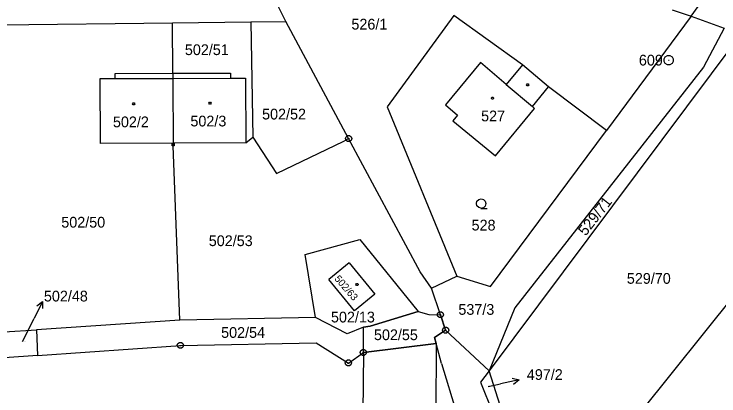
# Model space of a CAD drawing. Extents: x -759060 to -757386, y -1172273 to -1170948.
# Drawn here: x -758724.7 to -758613.1, y -1171917.2 to -1171856.8 of the extents above; entities that cross this region are included whole.
import ezdxf

# ---------------------------------------------------------------- set-up
doc = ezdxf.new("R2010")
doc.units = 0
for name, color, linetype in [('Vrstva 1', 7, 'Continuous'), ('Vrstva 12', 7, 'Continuous'), ('Vrstva 13', 7, 'Continuous'), ('Vrstva 2', 7, 'Continuous'), ('Vrstva 3', 7, 'Continuous'), ('Vrstva 4', 7, 'Continuous'), ('Vrstva 5', 7, 'Continuous'), ('Vrstva 7', 7, 'Continuous'), ('Vrstva 8', 7, 'Continuous')]:
    doc.layers.add(name, color=color, linetype=linetype)

msp = doc.modelspace()

# ---------------------------------------------------------------- linework, layer by layer
at = {"layer": 'Vrstva 1'}
for p, q in [((-758681.63, -1171857.97), (-758688.87, -1171843.64)), ((-758617.44, -1171857.11), (-758616.32, -1171855.59)), ((-758620.44, -1171856.14), (-758617.44, -1171857.11)), ((-758699.57, -1171858.18), (-758687.18, -1171858.03)), ((-758687.18, -1171858.03), (-758681.63, -1171857.97)), ((-758687.18, -1171858.03), (-758686.87, -1171876.27)), ((-758671.69, -1171876.51), (-758681.63, -1171857.97)), ((-758655.06, -1171857.01), (-758665.59, -1171871.5)), ((-758644.15, -1171864.85), (-758655.06, -1171857.01)), ((-758617.44, -1171857.11), (-758630.84, -1171875.22)), ((-758617.44, -1171857.11), (-758612.23, -1171859.02)), ((-758726.92, -1171858.5), (-758699.57, -1171858.18)), ((-758699.53, -1171866.17), (-758699.57, -1171858.18)), ((-758612.23, -1171859.02), (-758615.5, -1171865.18)), ((-758609.42, -1171859.7), (-758649.44, -1171913.23)), ((-758650.82, -1171864.46), (-758656.38, -1171871.16)), ((-758646.74, -1171867.94), (-758650.82, -1171864.46)), ((-758644.15, -1171864.85), (-758646.74, -1171867.94)), ((-758615.5, -1171865.18), (-758645.35, -1171903.31)), ((-758640.02, -1171868.34), (-758644.15, -1171864.85)), ((-758711.02, -1171867.01), (-758708.69, -1171867)), ((-758710.97, -1171877.29), (-758711.02, -1171867.01)), ((-758708.69, -1171866.21), (-758699.53, -1171866.17)), ((-758708.69, -1171867), (-758708.69, -1171866.21)), ((-758699.53, -1171866.17), (-758690.38, -1171866.14)), ((-758699.53, -1171866.17), (-758699.53, -1171866.97)), ((-758699.53, -1171866.97), (-758699.47, -1171877.64)), ((-758690.38, -1171866.14), (-758690.38, -1171866.94)), ((-758690.38, -1171866.94), (-758688.04, -1171866.94)), ((-758688.04, -1171866.94), (-758687.99, -1171877.18)), ((-758642.6, -1171871.41), (-758640.02, -1171868.34)), ((-758630.84, -1171875.22), (-758640.02, -1171868.34)), ((-758656.38, -1171871.16), (-758654.44, -1171872.8)), ((-758642.24, -1171871.75), (-758642.6, -1171871.41)), ((-758665.59, -1171871.5), (-758654.55, -1171898.27)), ((-758648.43, -1171879.21), (-758642.24, -1171871.75)), ((-758654.44, -1171872.8), (-758655.2, -1171873.68)), ((-758655.2, -1171873.68), (-758648.43, -1171879.21)), ((-758649.25, -1171899.92), (-758630.84, -1171875.22)), ((-758687.99, -1171877.18), (-758686.87, -1171876.27)), ((-758686.87, -1171876.27), (-758683.13, -1171882.02)), ((-758683.13, -1171882.02), (-758672.47, -1171876.89)), ((-758672.47, -1171876.89), (-758671.69, -1171876.51)), ((-758660.39, -1171897.59), (-758671.69, -1171876.51)), ((-758641.1, -1171939.36), (-758590.42, -1171876.04)), ((-758699.63, -1171877.24), (-758710.97, -1171877.29)), ((-758699.63, -1171877.64), (-758699.63, -1171877.24)), ((-758699.47, -1171877.64), (-758699.63, -1171877.64)), ((-758698.42, -1171905.23), (-758699.47, -1171877.64)), ((-758699.3, -1171877.64), (-758699.47, -1171877.64)), ((-758687.99, -1171877.18), (-758699.3, -1171877.24)), ((-758699.3, -1171877.24), (-758699.3, -1171877.64)), ((-758678.56, -1171894.85), (-758669.92, -1171892.47)), ((-758669.92, -1171892.47), (-758660.69, -1171903.85)), ((-758676.93, -1171904.8), (-758678.56, -1171894.85)), ((-758671.62, -1171896.16), (-758674.84, -1171898.79)), ((-758671.62, -1171896.16), (-758667.54, -1171901.15)), ((-758658.59, -1171900.15), (-758660.39, -1171897.59)), ((-758658.59, -1171900.15), (-758654.55, -1171898.27)), ((-758654.55, -1171898.27), (-758649.25, -1171899.92)), ((-758670.75, -1171903.77), (-758674.84, -1171898.79)), ((-758657.16, -1171904.38), (-758658.59, -1171900.15)), ((-758667.54, -1171901.15), (-758670.75, -1171903.77)), ((-758660.69, -1171903.85), (-758668.27, -1171906.2)), ((-758660.69, -1171903.85), (-758659, -1171904.32)), ((-758645.35, -1171903.31), (-758649.44, -1171913.23)), ((-758676.93, -1171904.8), (-758698.42, -1171905.23)), ((-758671.94, -1171907.4), (-758676.93, -1171904.8)), ((-758659, -1171904.32), (-758657.16, -1171904.38)), ((-758656.33, -1171906.83), (-758657.16, -1171904.38)), ((-758698.42, -1171905.23), (-758721.14, -1171906.79)), ((-758726.24, -1171907.11), (-758721.14, -1171906.79)), ((-758721.14, -1171906.79), (-758720.99, -1171910.81)), ((-758669.33, -1171906.33), (-758671.94, -1171907.4)), ((-758669.36, -1171910.35), (-758669.33, -1171906.33)), ((-758668.27, -1171906.2), (-758669.33, -1171906.33)), ((-758658.08, -1171907.96), (-758656.33, -1171906.83)), ((-758656.33, -1171906.83), (-758649.44, -1171913.23)), ((-758657.83, -1171908.92), (-758658.08, -1171907.96)), ((-758720.99, -1171910.81), (-758698.34, -1171909.23)), ((-758698.34, -1171909.23), (-758676.85, -1171908.8)), ((-758676.85, -1171908.8), (-758671.73, -1171912.02)), ((-758669.36, -1171910.35), (-758657.83, -1171908.92)), ((-758657.83, -1171908.92), (-758657.93, -1171926.59)), ((-758657, -1171912.1), (-758657.83, -1171908.92)), ((-758671.73, -1171912.02), (-758669.36, -1171910.35)), ((-758669.36, -1171910.35), (-758669.48, -1171926.67)), ((-758720.99, -1171910.81), (-758726.18, -1171911.22)), ((-758657, -1171912.1), (-758649.11, -1171937.91)), ((-758649.44, -1171913.23), (-758650.8, -1171915.04)), ((-758641.1, -1171939.36), (-758649.44, -1171913.23)), ((-758650.8, -1171915.04), (-758641.1, -1171939.36))]:
    msp.add_line(p, q, dxfattribs=at)
at = {"layer": 'Vrstva 12'}
for p, q in [((-758650.82, -1171864.46), (-758656.38, -1171871.16)), ((-758646.74, -1171867.94), (-758650.82, -1171864.46)), ((-758711.02, -1171867.01), (-758708.69, -1171867)), ((-758710.97, -1171877.29), (-758711.02, -1171867.01)), ((-758708.69, -1171867), (-758699.53, -1171866.97)), ((-758699.53, -1171866.97), (-758690.38, -1171866.94)), ((-758699.53, -1171866.97), (-758699.47, -1171877.64)), ((-758699.53, -1171866.97), (-758699.47, -1171877.64)), ((-758690.38, -1171866.94), (-758688.04, -1171866.94)), ((-758688.04, -1171866.94), (-758687.99, -1171877.18)), ((-758646.74, -1171867.94), (-758642.6, -1171871.41)), ((-758656.38, -1171871.16), (-758654.44, -1171872.8)), ((-758642.24, -1171871.75), (-758642.6, -1171871.41)), ((-758648.43, -1171879.21), (-758642.24, -1171871.75)), ((-758654.44, -1171872.8), (-758655.2, -1171873.68)), ((-758655.2, -1171873.68), (-758648.43, -1171879.21)), ((-758699.63, -1171877.24), (-758710.97, -1171877.29)), ((-758699.63, -1171877.64), (-758699.63, -1171877.24)), ((-758699.47, -1171877.64), (-758699.63, -1171877.64)), ((-758699.3, -1171877.64), (-758699.47, -1171877.64)), ((-758687.99, -1171877.18), (-758699.3, -1171877.24)), ((-758699.3, -1171877.24), (-758699.3, -1171877.64)), ((-758671.62, -1171896.16), (-758674.84, -1171898.79)), ((-758671.62, -1171896.16), (-758667.54, -1171901.15)), ((-758670.75, -1171903.77), (-758674.84, -1171898.79)), ((-758667.54, -1171901.15), (-758670.75, -1171903.77))]:
    msp.add_line(p, q, dxfattribs=at)
at = {"layer": 'Vrstva 13'}
for p, q in [((-758668.27, -1171906.2), (-758660.69, -1171903.85)), ((-758660.69, -1171903.85), (-758659, -1171904.32)), ((-758659, -1171904.32), (-758657.16, -1171904.38)), ((-758657.16, -1171904.38), (-758656.33, -1171906.83)), ((-758669.36, -1171910.35), (-758669.33, -1171906.33)), ((-758669.33, -1171906.33), (-758668.27, -1171906.2)), ((-758656.33, -1171906.83), (-758658.08, -1171907.96)), ((-758658.08, -1171907.96), (-758657.83, -1171908.92)), ((-758657.83, -1171908.92), (-758669.36, -1171910.35))]:
    msp.add_line(p, q, dxfattribs=at)
at = {"layer": 'Vrstva 3'}
msp.add_lwpolyline([(-758650.72, -1171887.53), (-758651.1, -1171887.43), (-758651.37, -1171887.16), (-758651.47, -1171886.79), (-758651.37, -1171886.42), (-758651.1, -1171886.15), (-758650.73, -1171886.05), (-758650.36, -1171886.15), (-758650.09, -1171886.42), (-758649.99, -1171886.8), (-758650.09, -1171887.18), (-758650.36, -1171887.45), (-758650.74, -1171887.55), (-758649.74, -1171887.55)], dxfattribs=at)
at = {"layer": 'Vrstva 4'}
for p, q in [((-758708.69, -1171867), (-758699.53, -1171866.97)), ((-758699.53, -1171866.97), (-758690.38, -1171866.94)), ((-758646.74, -1171867.94), (-758642.6, -1171871.41))]:
    msp.add_line(p, q, dxfattribs=at)
at = {"layer": 'Vrstva 5'}
for points in [[(-758643.24, -1171867.85), (-758643.15, -1171868), (-758643.24, -1171868.15), (-758643.42, -1171868.15), (-758643.51, -1171868), (-758643.42, -1171867.85)], [(-758648.82, -1171869.94), (-758648.73, -1171870.09), (-758648.82, -1171870.24), (-758649, -1171870.24), (-758649.09, -1171870.09), (-758649, -1171869.94)], [(-758705.66, -1171870.85), (-758705.57, -1171871), (-758705.66, -1171871.15), (-758705.84, -1171871.15), (-758705.93, -1171871), (-758705.84, -1171870.85)], [(-758693.57, -1171870.76), (-758693.48, -1171870.91), (-758693.57, -1171871.06), (-758693.75, -1171871.06), (-758693.84, -1171870.91), (-758693.75, -1171870.76)], [(-758670.26, -1171899.46), (-758670.17, -1171899.61), (-758670.26, -1171899.76), (-758670.44, -1171899.76), (-758670.53, -1171899.61), (-758670.44, -1171899.46)]]:
    msp.add_lwpolyline(points, close=True, dxfattribs=at)
at = {"layer": 'Vrstva 7'}
for p, q in [((-758720.185, -1171902.283), (-758721.52, -1171904.97)), ((-758723.33, -1171908.61), (-758721.52, -1171904.97)), ((-758644.712, -1171914.703), (-758647.65, -1171915.31)), ((-758649.61, -1171915.71), (-758647.65, -1171915.31))]:
    msp.add_line(p, q, dxfattribs=at)
for points in [[(-758721.078, -1171902.956), (-758720.185, -1171902.283), (-758720.182, -1171903.401)], [(-758645.792, -1171914.416), (-758644.712, -1171914.703), (-758645.59, -1171915.395)]]:
    msp.add_lwpolyline(points, dxfattribs=at)
at = {"layer": 'Vrstva 8'}
for p, q in [((-758621.05, -1171864.09), (-758620.95, -1171864.09)), ((-758671.81, -1171876.51), (-758671.57, -1171876.51)), ((-758657.28, -1171904.38), (-758657.04, -1171904.38)), ((-758656.45, -1171906.83), (-758656.21, -1171906.83)), ((-758698.46, -1171909.23), (-758698.22, -1171909.23)), ((-758669.48, -1171910.35), (-758669.24, -1171910.35)), ((-758671.85, -1171912.02), (-758671.61, -1171912.02))]:
    msp.add_line(p, q, dxfattribs=at)
for points in [[(-758620.81, -1171863.37), (-758620.47, -1171863.56), (-758620.28, -1171863.9), (-758620.28, -1171864.29), (-758620.47, -1171864.63), (-758620.81, -1171864.82), (-758621.2, -1171864.82), (-758621.54, -1171864.63), (-758621.73, -1171864.29), (-758621.73, -1171863.9), (-758621.54, -1171863.56), (-758621.2, -1171863.37)], [(-758671.54, -1171876.03), (-758671.29, -1171876.21), (-758671.19, -1171876.5), (-758671.29, -1171876.79), (-758671.54, -1171876.97), (-758671.85, -1171876.97), (-758672.1, -1171876.79), (-758672.2, -1171876.5), (-758672.1, -1171876.21), (-758671.85, -1171876.03)], [(-758657.01, -1171903.9), (-758656.76, -1171904.08), (-758656.66, -1171904.37), (-758656.76, -1171904.66), (-758657.01, -1171904.84), (-758657.32, -1171904.84), (-758657.57, -1171904.66), (-758657.67, -1171904.37), (-758657.57, -1171904.08), (-758657.32, -1171903.9)], [(-758656.18, -1171906.35), (-758655.93, -1171906.53), (-758655.83, -1171906.82), (-758655.93, -1171907.11), (-758656.18, -1171907.29), (-758656.49, -1171907.29), (-758656.74, -1171907.11), (-758656.84, -1171906.82), (-758656.74, -1171906.53), (-758656.49, -1171906.35)], [(-758698.19, -1171908.75), (-758697.94, -1171908.93), (-758697.84, -1171909.22), (-758697.94, -1171909.51), (-758698.19, -1171909.69), (-758698.5, -1171909.69), (-758698.75, -1171909.51), (-758698.85, -1171909.22), (-758698.75, -1171908.93), (-758698.5, -1171908.75)], [(-758669.21, -1171909.87), (-758668.96, -1171910.05), (-758668.86, -1171910.34), (-758668.96, -1171910.63), (-758669.21, -1171910.81), (-758669.52, -1171910.81), (-758669.77, -1171910.63), (-758669.87, -1171910.34), (-758669.77, -1171910.05), (-758669.52, -1171909.87)], [(-758671.58, -1171911.54), (-758671.33, -1171911.72), (-758671.23, -1171912.01), (-758671.33, -1171912.3), (-758671.58, -1171912.48), (-758671.89, -1171912.48), (-758672.14, -1171912.3), (-758672.24, -1171912.01), (-758672.14, -1171911.72), (-758671.89, -1171911.54)]]:
    msp.add_lwpolyline(points, close=True, dxfattribs=at)

# ---------------------------------------------------------------- texts
at = {"layer": 'Vrstva 2'}
for s, height, p in [('526/1', 1.7, (-758671.253, -1171859.25)), ('502/51', 1.7, (-758697.629, -1171863.29)), ('502/52', 1.7, (-758685.4, -1171873.48)), ('527', 1.7, (-758650.713, -1171873.77)), ('502/2', 1.7, (-758709.023, -1171874.71)), ('502/3', 1.7, (-758696.753, -1171874.58)), ('502/50', 1.7, (-758717.203, -1171890.59)), ('528', 1.7, (-758652.223, -1171891.05)), ('502/53', 1.7, (-758693.844, -1171893.52)), ('529/70', 1.7, (-758627.633, -1171899.48)), ('537/3', 1.7, (-758654.313, -1171904.39)), ('502/13', 1.7, (-758674.493, -1171905.6)), ('502/54', 1.7, (-758691.887, -1171908.04)), ('502/55', 1.7, (-758667.684, -1171908.4)), ('502/48', 0.1, (-758723.316, -1171908.61)), ('497/2', 0.1, (-758649.596, -1171915.71))]:
    msp.add_text(s, height=height, dxfattribs=at).set_placement(p)
for s, height, rotation, p in [('529/71', 1.7, 51.96727, (-758634.154, -1171892.013)), ('502/63', 1.14, 310.8296, (-758674.02, -1171898.729))]:
    msp.add_text(s, height=height, rotation=rotation, dxfattribs=at).set_placement(p)
at = {"layer": 'Vrstva 7'}
for s, p in [('502/48', (-758719.953, -1171902.28)), ('497/2', (-758643.473, -1171914.7))]:
    msp.add_text(s, height=1.7, dxfattribs=at).set_placement(p)
at = {"layer": 'Vrstva 8'}
msp.add_text('609', height=1.7, dxfattribs=at).set_placement((-758625.727, -1171864.94))

doc.saveas('drawing.dxf')
